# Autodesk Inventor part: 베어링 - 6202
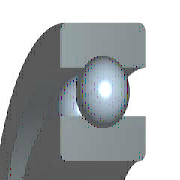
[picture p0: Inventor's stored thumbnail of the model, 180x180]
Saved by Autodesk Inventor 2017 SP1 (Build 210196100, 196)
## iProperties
IsCustomPart: 1
Created: 2015-09
Part Number: 베어링 - 6202
Material: 강, 연강
Description: 깊은 그루브 볼 베어링
Document SubType Name: Modeling
Standard: KS B 2023
Designer: mduedu
Standards Organization: KS
Language: ko-KR
Size Designation: 6202 - 15 x 35 x 11
Categories: <MemberInstance><Categories><Category DisplayName="샤프트 부품" InternalName="7f7aeb1f-a693-4053-b835-cee3144e0d98" Mnemonic="SHFT"><Category DisplayName="베어링" Inter
Density: 7.86 g/cm^3
Mass: 45.8725 g
Surface Area: 51.5584 cm^2
Volume: 5.83619 cm^3
Appearance: 노란색
Author: mduedu
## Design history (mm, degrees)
sketch "스케치" dims "d0" = 5.2 (= -0.26 x WD + 0.26 x BD)
  geometry: L1 (2.9, 12.5)-(8.1, 12.5); L2 (5.5, 12.5)-(5.5, 9.9); L3 (5.5, 12.5)-(5.5, 15.1); L4 (3.568, 10.76)-(0, 10.76); L5 (0, 7.5)-(11, 7.5); L6 (3.568, 14.24)-(0, 14.24); L7 (0, 17.5)-(11, 17.5); L8 (11, 7.5)-(11, 10.76); L9 (7.432, 10.76)-(11, 10.76); L10 (7.432, 14.24)-(11, 14.24); L11 (11, 17.5)-(11, 14.24); L12 (-1.4, 0)-(8.4, 0) reference; L13 (0, -0.3)-(0, 5.3) reference
  constraints: 22 end point, 4 point on line, 2 collinear, 2 perpendicular, 2 symmetric about line, 1 midpoint, 1 parallel, 14 other
  dimensions: "d9" = 15 diameter of L5 L12 (= WD); "d11" = 35 diameter of L7 L12 (= BD); "d12" = 11 distance between parallel lines of L8 L13 (= KB); "d13" = 21.52 diameter of L9 L12 (= 0.326 x BD + 0.674 x WD)
revolve "본체" stored, may be unused: angle "d6" = 90 deg
revolve "볼" stored, may be unused: angle "d7" = 90 deg
pattern_circular "IDS_ARRAYBALL[SIMPL:T]" dims angle "d3" = 360 deg
body "Solid1"
fillet "모깎기1" dims "d1" = 0.6 (= KRS)
other parameters: "WD" = 15 [user parameter; used in 5 equation terms], "BD" = 35 [user parameter; used in 5 equation terms], "KB" = 11 [user parameter; used in 1 equation term], "KRS" = 0.6 [user parameter; used in 1 equation term], "d4" = 0, "d5" = 0, "d8" = 0, "d14" = 0, "d15" = 0, "BBA" = 0 [user parameter], "BC0" = 3750000 [user parameter], "BC" = 7800000 [user parameter], "BR" = 17.5 (= 0.5 x BD) [user parameter], "WR" = 7.5 (= 0.5 x WD) [user parameter]
